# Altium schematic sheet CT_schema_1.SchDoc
size 542 x 288 mm
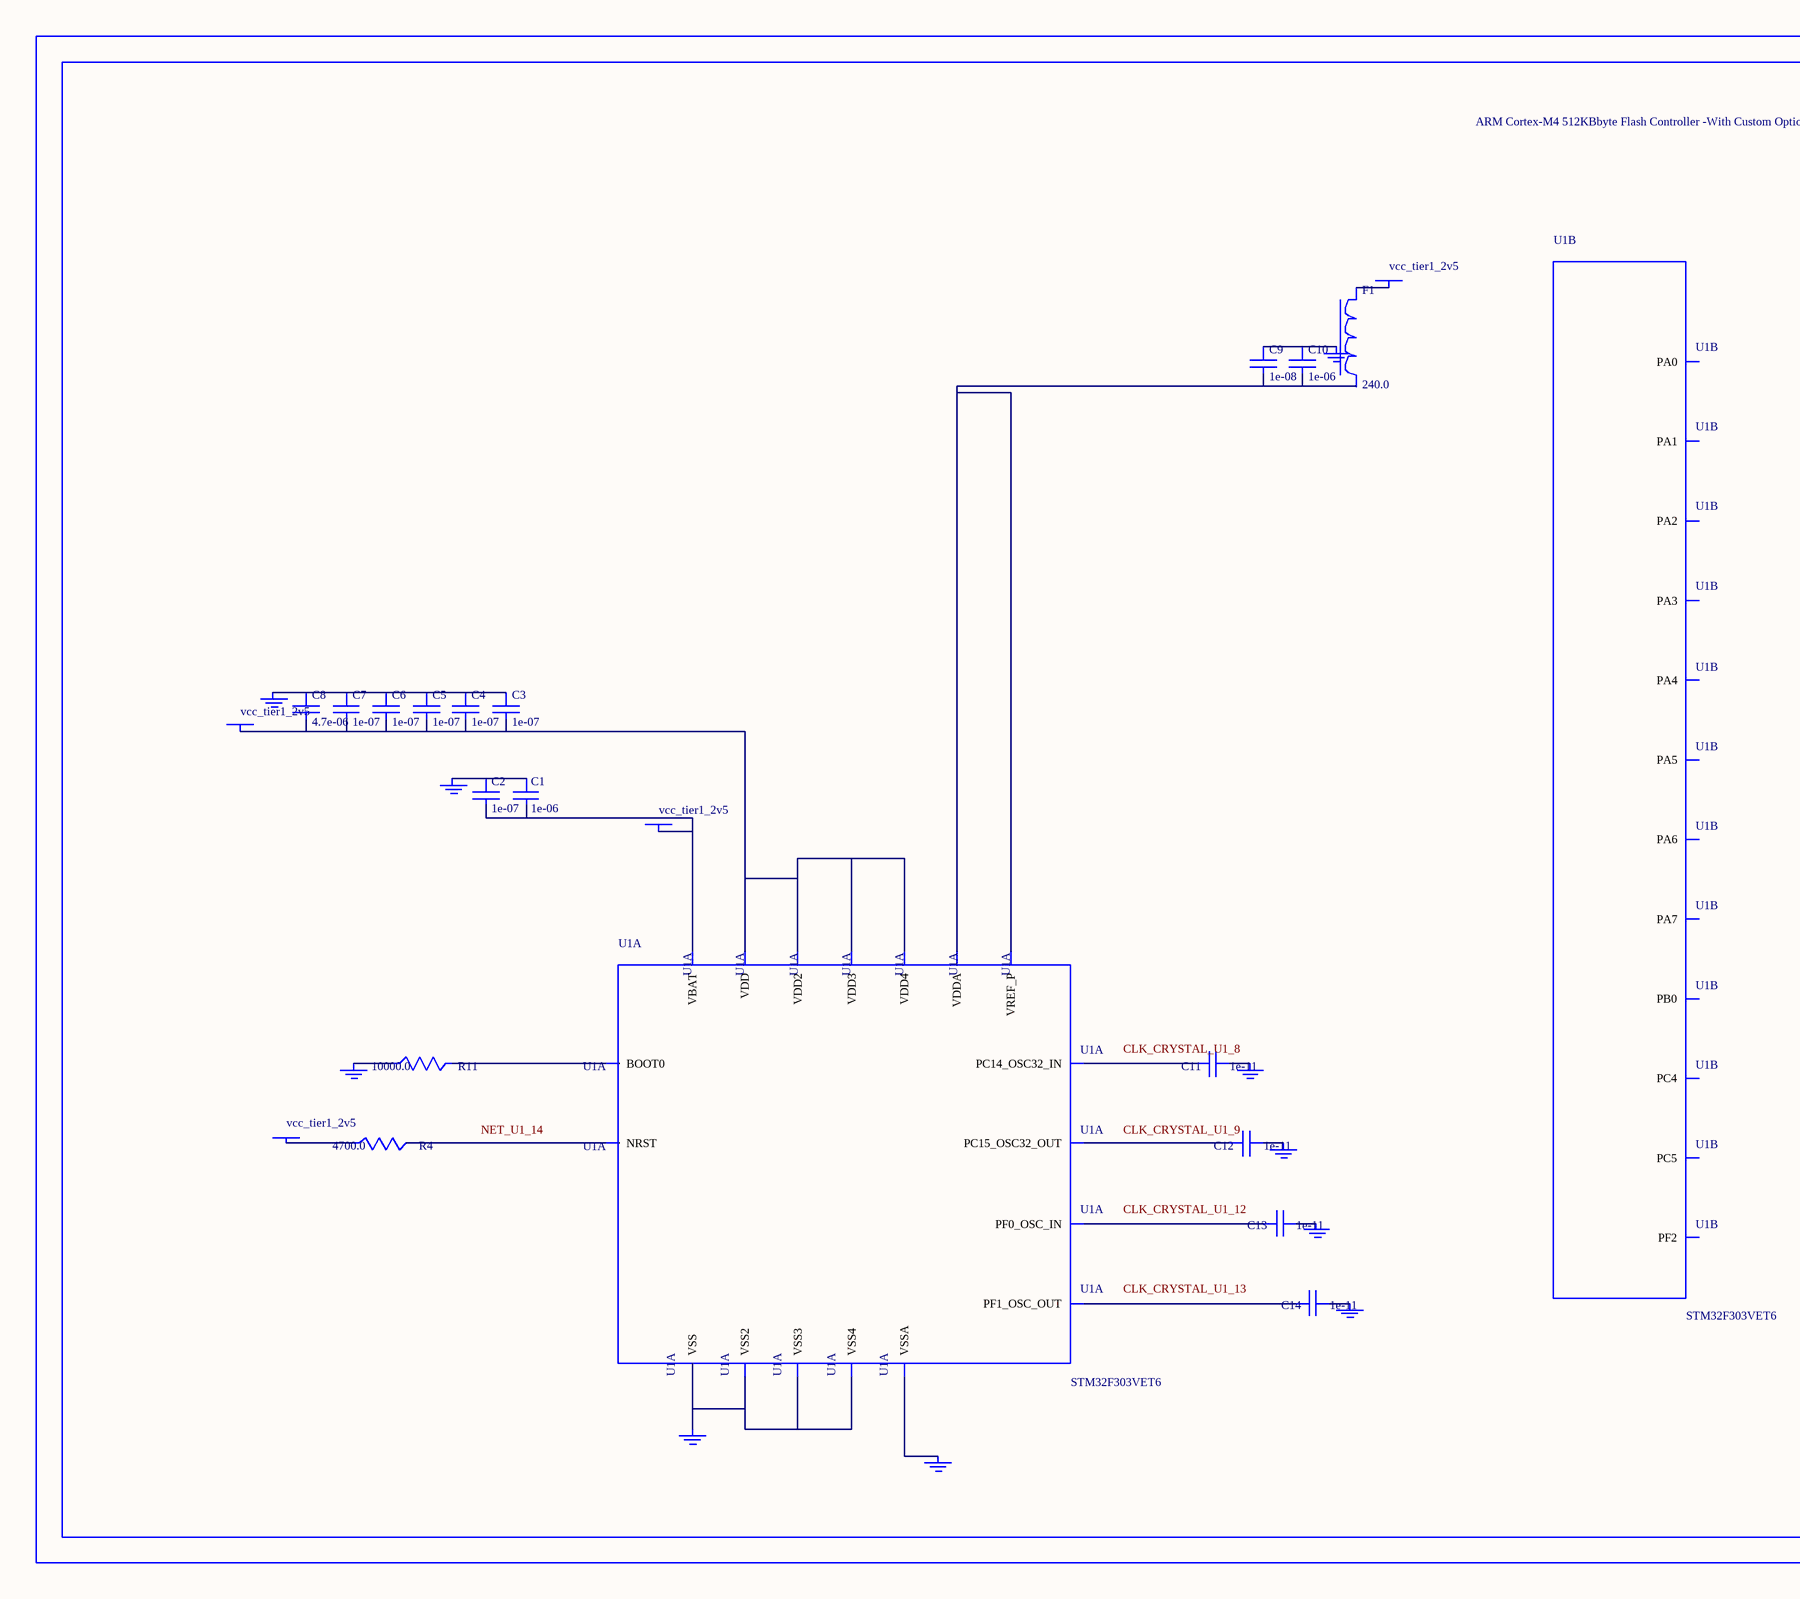
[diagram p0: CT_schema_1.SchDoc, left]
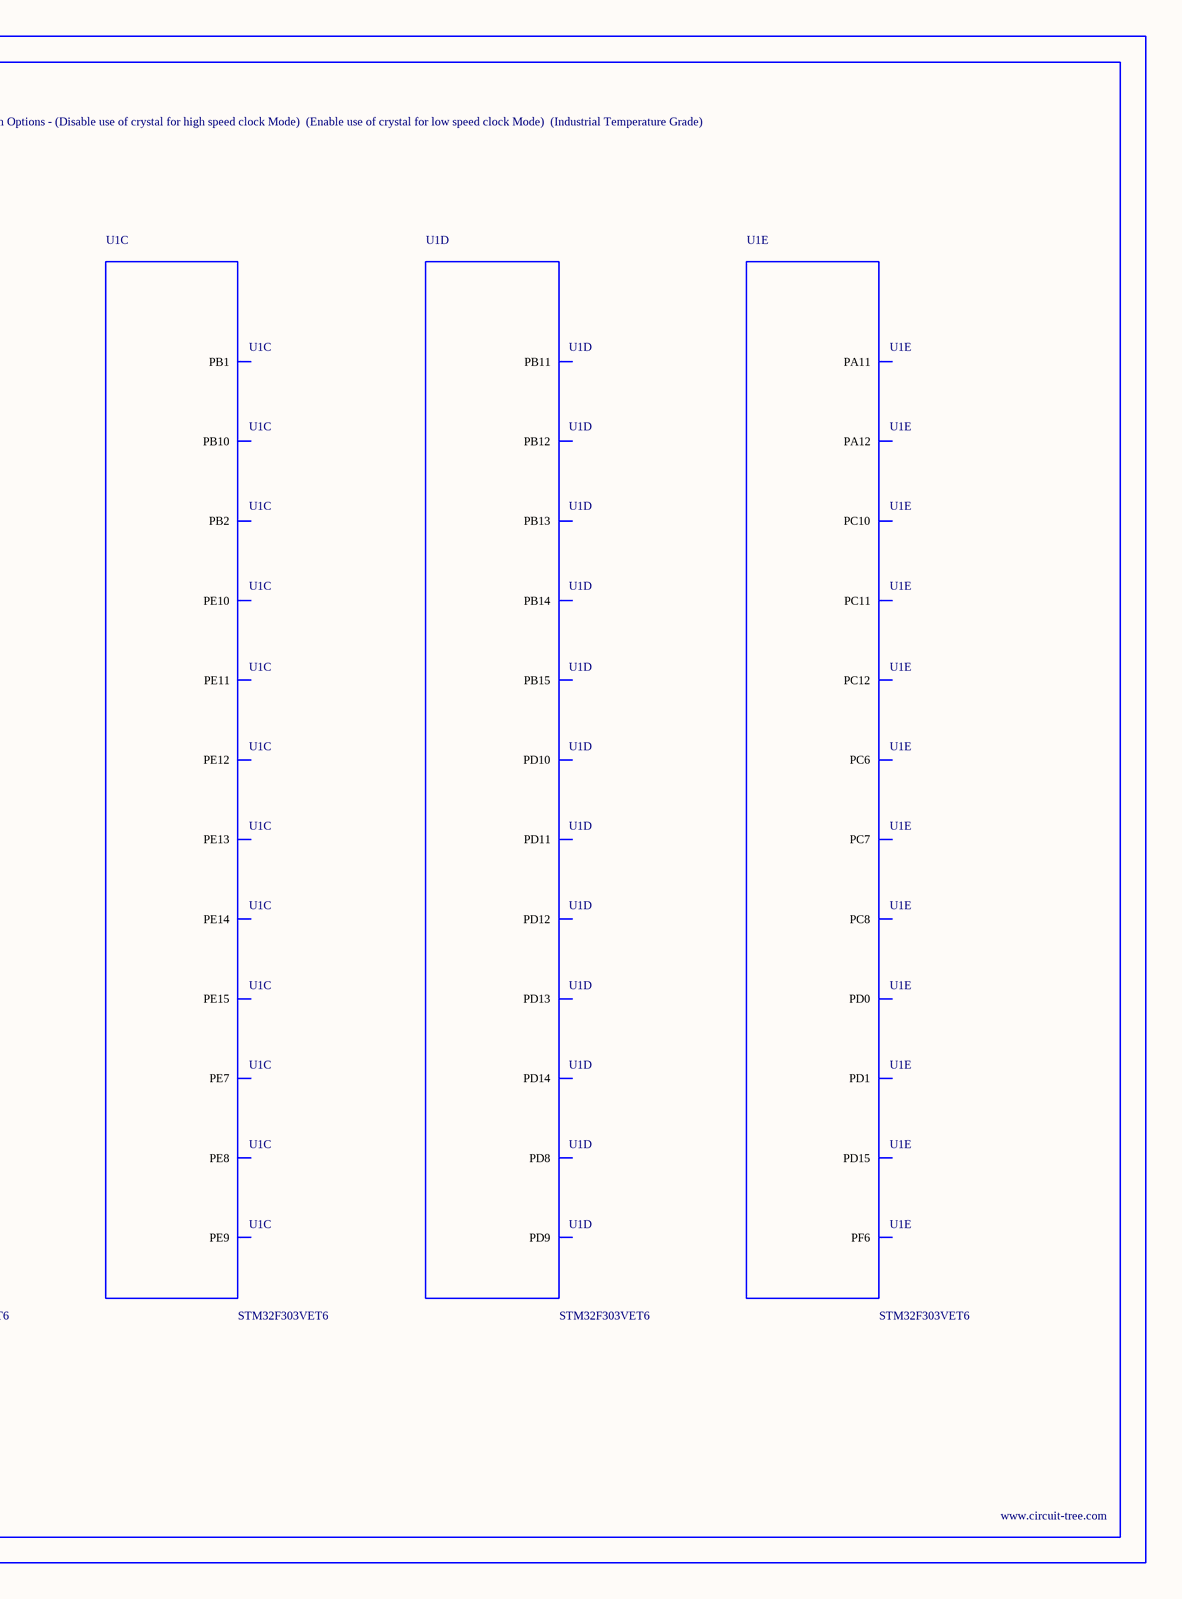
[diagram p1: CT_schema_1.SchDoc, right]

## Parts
BORDER0  (no value)
C1  1e-06  [C0603]
C2  1e-07  [C0603]
C3  1e-07  [C0603]
C4  1e-07  [C0603]
C5  1e-07  [C0603]
C6  1e-07  [C0603]
C7  1e-07  [C0603]
C8  4.7e-06  [C0603]
C9  1e-08  [C0603]
C10  1e-06  [C0603]
C11  1e-11  [C0402]
C12  1e-11  [C0402]
C13  1e-11  [C0402]
C14  1e-11  [C0402]
F1  240.0  [L0603]
GND_INSTANCE_0_0  (no value)
GND_INSTANCE_0_1  (no value)
GND_INSTANCE_0_2  (no value)
GND_INSTANCE_0_3  (no value)
GND_INSTANCE_0_4  (no value)
GND_INSTANCE_0_5  (no value)
GND_INSTANCE_0_6  (no value)
GND_INSTANCE_0_7  (no value)
GND_INSTANCE_0_8  (no value)
GND_INSTANCE_0_9  (no value)
POWER_INSTANCE_0_0  vcc_tier1_2v5
POWER_INSTANCE_0_1  vcc_tier1_2v5
POWER_INSTANCE_0_2  vcc_tier1_2v5
POWER_INSTANCE_0_3  vcc_tier1_2v5
R4  4700.0  [R0603]
R11  10000.0  [R0603]
U1  STM32F303VET6  [LQFP100]  (parts A,B,C,D,E of 9)

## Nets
NetC1_1: C1.1 C2.1 GND_INSTANCE_0_0.0(GND)
NetC1_2: C1.2 C2.2 POWER_INSTANCE_0_0.0(PWR) U1.6(VBAT)
NetC3_1: C3.1 C4.1 C5.1 C6.1 C7.1 C8.1 GND_INSTANCE_0_7.0(GND)
NetC3_2: C3.2 C4.2 C5.2 C6.2 C7.2 C8.2 POWER_INSTANCE_0_2.0(PWR) U1.28(VDD) U1.50(VDD2) U1.75(VDD3) U1.100(VDD4)
NetC9_1: C9.1 C10.1 GND_INSTANCE_0_6.0(GND)
NetC9_2: C9.2 C10.2 U1.21(VREF_P) U1.22(VDDA)
NetC11_1: C11.1 GND_INSTANCE_0_1.0(GND)
NetC11_2: C11.2 U1.8(PC14_OSC32_IN)
NetC12_1: C12.1 GND_INSTANCE_0_2.0(GND)
NetC12_2: C12.2 U1.9(PC15_OSC32_OUT)
NetC13_1: C13.1 GND_INSTANCE_0_3.0(GND)
NetC13_2: C13.2 U1.12(PF0_OSC_IN)
NetC14_1: C14.1 GND_INSTANCE_0_4.0(GND)
NetC14_2: C14.2 U1.13(PF1_OSC_OUT)
NetF1_1: F1.1 POWER_INSTANCE_0_1.0(PWR)
NetGND_INSTANCE_0_5_0: GND_INSTANCE_0_5.0(GND) U1.20(VSSA)
NetGND_INSTANCE_0_8_0: GND_INSTANCE_0_8.0(GND) R11.1
NetGND_INSTANCE_0_9_0: GND_INSTANCE_0_9.0(GND) U1.27(VSS) U1.49(VSS2) U1.74(VSS3) U1.99(VSS4)
NetPOWER_INSTANCE_0_3_0: POWER_INSTANCE_0_3.0(PWR) R4.1
NetR4_2: R4.2 U1.14(NRST)
NetR11_2: R11.2 U1.94(BOOT0)

Not connected (* = marked no-connect by the designer): F1 2; U1 19(PF2) 23(PA0) 24(PA1) 25(PA2) 26(PA3) 29(PA4) 30(PA5) 31(PA6) 32(PA7) 33(PC4) 34(PC5) 35(PB0) 36(PB1) 37(PB2) 38(PE7) 39(PE8) 40(PE9) 41(PE10) 42(PE11) 43(PE12) 44(PE13) 45(PE14) 46(PE15) 47(PB10) 48(PB11) 51(PB12) 52(PB13) 53(PB14) 54(PB15) 55(PD8) 56(PD9) 57(PD10) 58(PD11) 59(PD12) 60(PD13) 61(PD14) 62(PD15) 63(PC6) 64(PC7) 65(PC8) 70(PA11) 71(PA12) 73(PF6) 78(PC10) 79(PC11) 80(PC12) 81(PD0) 82(PD1)

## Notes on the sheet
- Labels drawn without touching a wire or pin: CLK_CRYSTAL_U1_8, CLK_CRYSTAL_U1_9, CLK_CRYSTAL_U1_12, CLK_CRYSTAL_U1_13, NET_U1_14

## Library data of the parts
BORDER0 = BORDER_PAGE0
C1 C10 = C0603C105K3RACTU
C2-C7 = 06035C104K4Z2A
C8 = GRM188R6YA475KE15D
C9 = 06035C103K4Z2A
C11-C14 = C0402C100K3GACTU
F1 = Z0603C241ASMST
GND_INSTANCE_0_0-GND_INSTANCE_0_9 = GND
POWER_INSTANCE_0_0-POWER_INSTANCE_0_3 = PWR
R4 = RC0603JR-074K7L
R11 = RC0603JR-0710KL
